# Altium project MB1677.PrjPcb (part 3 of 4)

## Sheet Board_power.SchDoc: Board power
size A4; Date: Not used; ApprovedBy: Not used; CheckedBy: Not used; Author: Not used; CompanyName: STMicroelectronics; DrawnBy: Not used; Engineer: Not used; Organization: Not used; Address1: Not used; Address2: Not used; Address3: Not used; Address4: Not used; DocumentNumber: 5; Revision: Not used; SheetNumber: 5; SheetTotal: 15
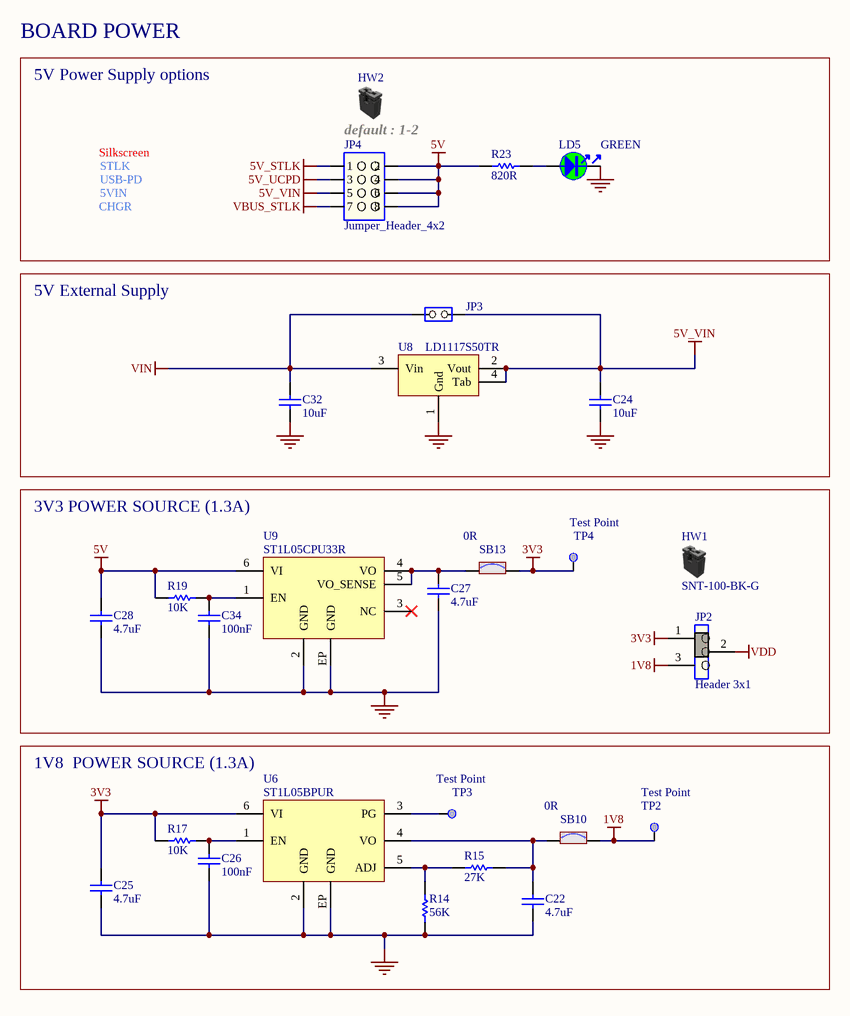
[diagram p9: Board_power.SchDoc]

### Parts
C22  value 4.7uF  [C0603]  (hidden comment: Capacitor)
C24  value 10uF  [C0805]  (hidden comment: Capacitor)
C25  value 4.7uF  [C0603]  (hidden comment: Capacitor)
C26  value 100nF  [C0402]  (hidden comment: Capacitor)
C27  value 4.7uF  [C0603]  (hidden comment: Capacitor)
C28  value 4.7uF  [C0603]  (hidden comment: Capacitor)
C32  value 10uF  [C0805]  (hidden comment: Capacitor)
C34  value 100nF  [C0402]  (hidden comment: Capacitor)
HW1  value SNT-100-BK-G  (hidden comment: Shunt Black 2.54mm)  (mechanical)
HW2  Shunt Black 2.54mm  (value not drawn)  (mechanical)
JP2  value Header 3x1  [CON_SAMTEC_TSW-103-07-F-S]  (hidden comment: Jumper_Header 3x1 Fitted 1-2)
JP3  Jumper_Header 2x1  [CON_SAMTEC_TSW-102-07-G-S]  (value not drawn)
JP4  value Jumper_Header_4x2  [CON_SAMTEC_TSM-104-01-X-DV]  (hidden comment: Jumper_Header 4x2)
LD5  value GREEN  [LED_0603_VISHAY_VLMTG1300-GS08_GREEN_1A2K_H0P8]  (hidden comment: LED_green)
R14  value 56K  [R0402]  (hidden comment: Resistor)
R15  value 27K  [R0402]  (hidden comment: Resistor)
R17  value 10K  [R0402]  (hidden comment: Resistor)
R19  value 10K  [R0402]  (hidden comment: Resistor)
R23  value 820R  [R0603]  (hidden comment: Resistor)
SB10  value 0R  [SOLDER-BRIDGE_R0603-0R]  (hidden comment: SB_ON)
SB13  value 0R  [SOLDER-BRIDGE_R0603-0R]  (hidden comment: SB_ON)
TP2  Test Point  [TP_SMD_2MM]  (no BOM)
TP3  Test Point  [TP_SMD_2MM]  (no BOM)
TP4  Test Point  [TP_SMD_2MM]  (no BOM)
U6  ST1L05BPUR  [ICC_DFN6-EPAD_3X3_P095]
U8  LD1117S50TR  [REG_SOT223-TAB]
U9  ST1L05CPU33R  [ICC_DFN6-EPAD_3X3_P095]

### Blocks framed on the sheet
BOARD POWER: HW2 JP4 LD5 R23
5V External Supply: C24 C32 JP3 U8
3V3 POWER SOURCE (1.3A): C27 C28 C34 HW1 JP2 R19 SB13 TP4 U9
1V8  POWER SOURCE (1.3A): C22 C25 C26 R14 R15 R17 SB10 TP2 TP3 U6

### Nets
1V8: JP2.3 SB10.2 TP2.1
3V3: C25.1 JP2.1 R17.1 SB13.2 TP4.1 U6.6(VI)
5V: C28.2 JP4.2 JP4.4 JP4.6 JP4.8 R19.1 R23.1 U9.6(VI)
5V_STLK: JP4.1
5V_UCPD: JP4.3
5V_VIN: C24.2 JP3.2(NO) JP4.5 U8.2(Vout) U8.4(Tab)
GND: C22.1 C24.1 C25.2 C26.1 C27.1 C28.1 C32.1 C34.1 LD5.2 R14.1 U6.2(GND) U6.EP(GND) U8.1(Gnd) U9.2(GND) U9.EP(GND)
VBUS_STLK: JP4.7
VDD: JP2.2
VIN: C32.2 JP3.1(COMMON) U8.3(Vin)
NetC22_2: C22.2 R15.2 SB10.1 U6.4(VO)
NetC26_2: C26.2 R17.2 U6.1(EN)
NetC27_2: C27.2 SB13.1 U9.4(VO) U9.5(VO_SENSE)
NetC34_2: C34.2 R19.2 U9.1(EN)
NetLD5_1: LD5.1 R23.2
NetR14_2: R14.2 R15.1 U6.5(ADJ)
NetTP3_1: TP3.1 U6.3(PG)

Not connected (* = marked no-connect by the designer): U9 3(NC)*

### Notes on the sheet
- 5V Power Supply options
- Silkscreen
- default : 1-2
- CHGR
- STLK
- USB-PD
- 5VIN

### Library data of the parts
C22 C25 C27 C28 = MCD-00009: Capacitor, MLCC, 4.7uF, 16V, X5R, +/-10%, 0603, T=0.8mm; Manufacturer_Part_Number: CC0603KRX5R7BB475; Manufacturer: YAGEO; Part_Preference: Recommended; Partial_Alternate_Internal_Part_Number: MCD-03565; Alternate_EMS: A; Component_Country_Of_Origin: China; ID: 2471; ShowFields: YES
C24 C32 = MCD-00014: Capacitor, MLCC, 10uF, 25V, X5R, 10%, 0805, T=0,85mm; Manufacturer_Part_Number: CC0805KRX5R8BB106; Manufacturer: YAGEO; Full_Alternate_Internal_Part_Number: MCD-02385; Part_Preference: Recommended; Partial_Alternate_Internal_Part_Number: MCD-03053; Provided_By: SUBCO; Component_Country_Of_Origin: China; ID: 2468; ShowFields: YES
C26 C34 = MCD-00006: Capacitor, MLCC, 100nF, 16V, X7R, +/-10%, 0402, T=0.5mm; Manufacturer_Part_Number: CC0402KRX7R7BB104; Manufacturer: YAGEO; Part_Preference: Recommended; Partial_Alternate_Internal_Part_Number: MCD-03299; Component_Country_Of_Origin: China; ID: 2474; Order_Code_RS: 9402047; ShowFields: YES
HW1 = MCD-00043: SHUNT 2.54mm BLACK; Part_Type: Misc; Part_Preference: Recommended; Manufacturer: SAMTEC; Alternate_Manufacturer: JIUBABA; Alternate_Manufacturer_Part_Number: 316102S111A; Full_Alternate_Internal_Part_Number: MCD-02388; Manufacturer_HQ_COO: Unknown; Partial_Alternate_Internal_Part_Number: MCD-01849; Alternate_EMS: A; Component_Country_Of_Origin: China, Costa Rica, Malaysia, USA, Vietnam; ID: 2551; Order_Code_RS: 158-7784; ShowFields: YES
HW2 = MCD-00043: SHUNT 2.54mm BLACK; Part_Type: Misc; Manufacturer: SAMTEC; Alternate_Manufacturer_Part_Number: 316102S111A; Alternate_Manufacturer: JIUBABA; Full_Alternate_Internal_Part_Number: MCD-02388; Manufacturer_HQ_COO: Unknown; Part_Preference: Recommended; Partial_Alternate_Internal_Part_Number: MCD-01849; Value: SNT-100-BK-G; Provided_By: SUBCO; Alternate_EMS: A; Component_Country_Of_Origin: China, Costa Rica, Malaysia, USA, Vietnam; ID: 2551; Order_Code_RS: 158-7784; ShowFields: YES
JP2 = MCD-00684: Header, 3x1, 2,54mm, VR, TH, Height 5.84mm/2.54mm - Shunt Fitted 1-2 by default; Part_Type: Connector; Part_Preference: Recommended; Manufacturer: SAMTEC; Manufacturer_Part_Number: TSW-103-07-F-S; Partial_Alternate_Internal_Part_Number: MCD-03595, MCD-03723; Alternate_EMS: A; Component_Country_Of_Origin: China, Costa Rica, Malaysia, USA, Vietnam; ID: 3059; Order_Code_RS: 161-2248; ShowFields: YES
JP3 = MCD-00045: Header, 2x1, 2,54mm, VR, TH, Height 5.84mm/2.54mm; Part_Type: Connector; Manufacturer_Part_Number: TSW-102-07-G-S; Manufacturer: SAMTEC; Full_Alternate_Internal_Part_Number: MCD-02390; Part_Preference: Recommended; Partial_Alternate_Internal_Part_Number: MCD-02957, MCD-03720; Provided_By: Subcon; Initial_Board_Reference: MB1274; Remark: 3D KO: BZ: 40098; Component_Country_Of_Origin: China, Costa Rica, Malaysia, USA, Vietnam; ID: 2545; Order_Code_RS: 2505044; ShowFields: YES
JP4 = MCD-00044: Header, 4x2, 2,54mm, VR, SMT, Height 5.84mm/2.54mm; Part_Type: Connector; Part_Preference: Recommended; Manufacturer: SAMTEC; Manufacturer_Part_Number: TSM-104-01-G-DV; Component_Country_Of_Origin: China, Costa Rica, Malaysia, USA, Vietnam; ID: 2548; Order_Code_RS: 2578717; ShowFields: YES
LD5 = MCD-00589: LED Green, 0603 SMD, Fw Voltage = 2.8V - 3.6V; Part_Type: Display; Manufacturer_Part_Number: VLMTG1300-GS08; Manufacturer: VISHAY; Alternate_Manufacturer_Part_Number: LG Q396-PS-35; Alternate_Manufacturer: OSRAM OPTO SEMICONDUCTORS; Part_Preference: Recommended; Order_Code_RS: 7730452; Provided_By: SUBCO; Component_Country_Of_Origin: China; ID: 3157; ShowFields: YES
R14 = MCD-00493: Resistor,56K,0402,1%,1/16W; Part_Preference: Recommended; Manufacturer: YAGEO; Manufacturer_Part_Number: RC0402FR-0756KL; Component_Country_Of_Origin: China; ID: 2784; ShowFields: YES
R15 = MCD-00443: Resistor,27K,0402,1%,1/16W; Part_Preference: Recommended; Manufacturer: YAGEO; Manufacturer_Part_Number: RC0402FR-0727KL; Component_Country_Of_Origin: China; ID: 2834; ShowFields: YES
R17 R19 = MCD-00053: Resistor,10K,0402,1%,1/16W; Manufacturer_Part_Number: RC0402FR-0710KL; Manufacturer: YAGEO; BMS_Part_Number: 9131590; Part_Preference: Recommended; Provided_By: SUBCO; Component_Country_Of_Origin: China; ID: 2539; Order_Code_RS: 9239359; ShowFields: YES
R23 = MCD-00528: Resistor,820R,0603,1%,1/10W; Manufacturer_Part_Number: RC0603FR-07820RL; Manufacturer: YAGEO; BMS_Part_Number: 9129759; Part_Preference: Recommended; Provided_By: SUBCO; Component_Country_Of_Origin: China; ID: 3218; ShowFields: YES
SB10 SB13 = MCD-00071: Resistor, 0R, SB0603, 5%, 0.1W; Manufacturer_Part_Number: RC0603JR-070RL; Manufacturer: YAGEO; Manufacturer_HQ_COO: Unknown; Part_Preference: Recommended; Component_Country_Of_Origin: China; ID: 2521; Order_Code_RS: 199-5647; ShowFields: YES
TP2-TP4 = MCD-00177: Test Point 2mm; Part_Type: Misc; Part_Preference: Recommended; Component_Country_Of_Origin: Unknown; ID: 2690; ShowFields: YES
U6 = MCD-00581: LDO Linear Voltage Regulator IC Positive Adjustable 1 Output Adjustable 1.3A 6-DFN (3x3); BMS_Part_Number: 9176239; Part_Preference: Recommended; Manufacturer: STMICROELECTRONICS; Manufacturer_HQ_COO: EU; Component_Country_Of_Origin: Malaysia; ID: 3163; Order_Code_RS: 188-9209; ShowFields: YES
U8 = MCD-00088: IC REG LDO 5V 0.8A SOT223; Manufacturer: STMICROELECTRONICS; BMS_Part_Number: 9176133; Manufacturer_HQ_COO: EU; Part_Preference: Recommended; Provided_By: SUBCO with ST control; Component_Country_Of_Origin: China; ID: 2503; Order_Code_RS: 165-7748; ShowFields: YES
U9 = MCD-01025: LDO, 3.3V, 1.3A, Very low quiescent current BiCMOS voltage regulator; Part_Type: IC; Manufacturer: STMICROELECTRONICS; BMS_Part_Number: 9176246; Manufacturer_HQ_COO: EU; Part_Preference: Recommended; Provided_By: SUBCO with ST control; Component_Country_Of_Origin: Malaysia; ID: 2998; ShowFields: YES

## Sheet STM32_microcontroller_power.SchDoc: STM32 microcontroller power
size A4; Date: Not used; ApprovedBy: Not used; CheckedBy: Not used; Author: Not used; CompanyName: STMicroelectronics; DrawnBy: Not used; Engineer: Not used; Organization: Not used; Address1: Not used; Address2: Not used; Address3: Not used; Address4: Not used; DocumentNumber: 4; Revision: Not used; SheetNumber: 4; SheetTotal: 15
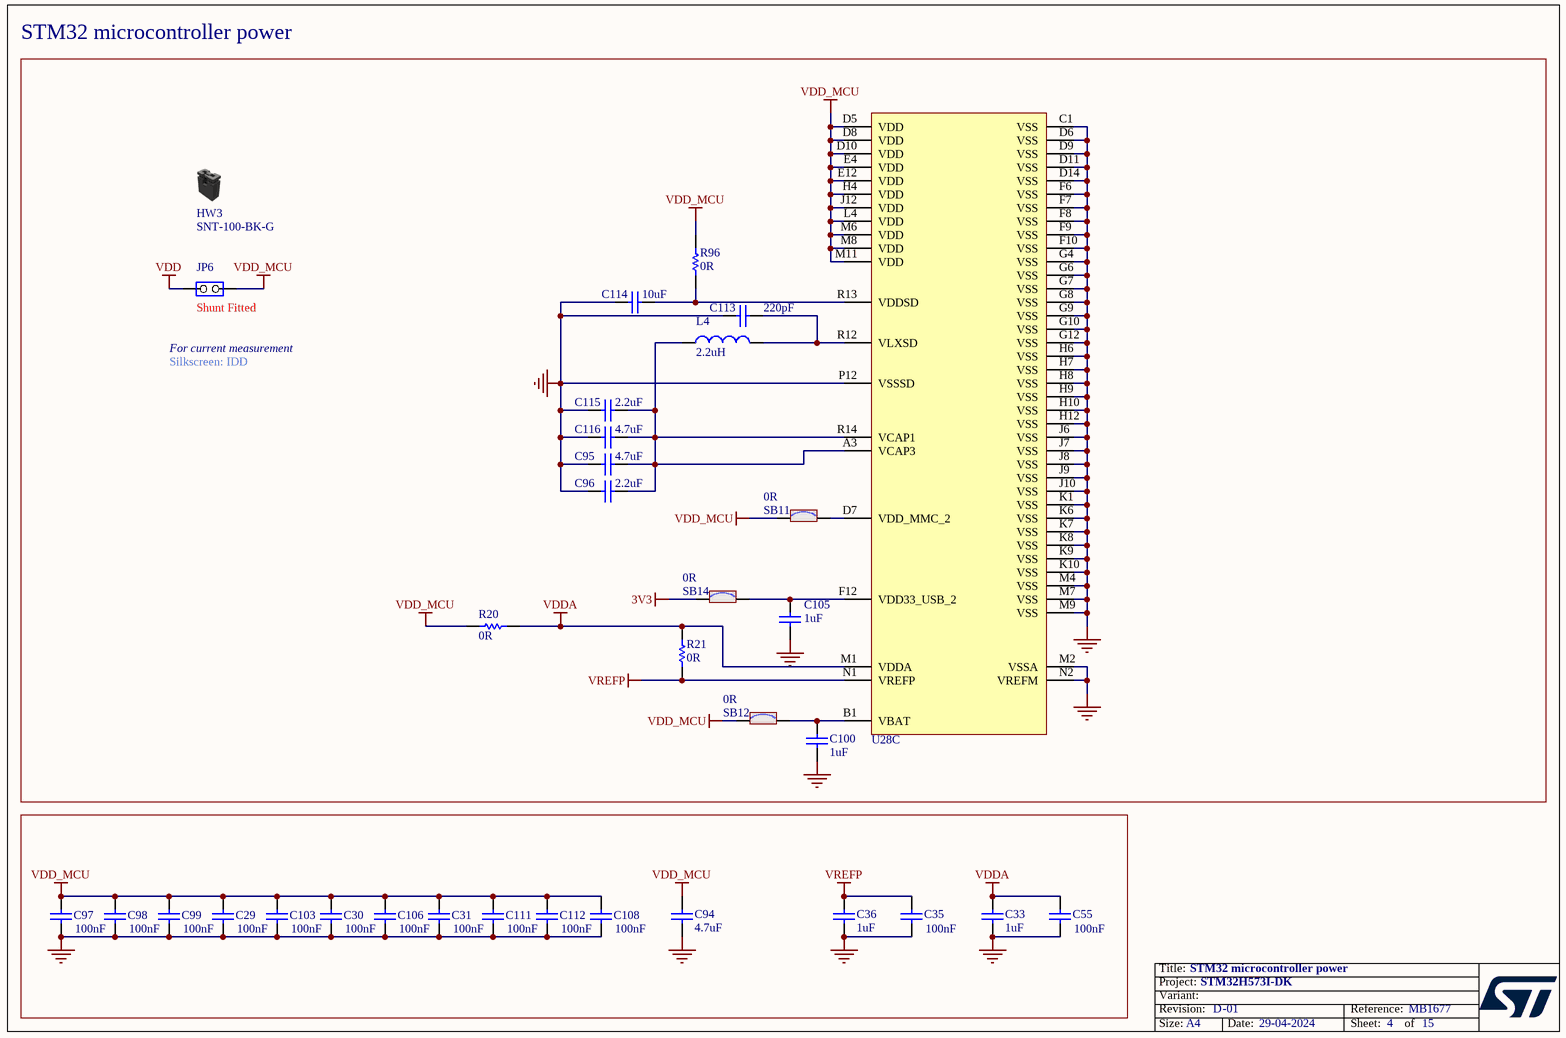
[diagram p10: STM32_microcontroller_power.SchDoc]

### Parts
C29  value 100nF  [C0402]  (hidden comment: Capacitor)
C30  value 100nF  [C0402]  (hidden comment: Capacitor)
C31  value 100nF  [C0402]  (hidden comment: Capacitor)
C33  value 1uF  [C0402]  (hidden comment: Capacitor)
C35  value 100nF  [C0402]  (hidden comment: Capacitor)
C36  value 1uF  [C0402]  (hidden comment: Capacitor)
C55  value 100nF  [C0402]  (hidden comment: Capacitor)
C94  value 4.7uF  [C0603]  (hidden comment: Capacitor)
C95  value 4.7uF  [C0402]  (hidden comment: Capacitor)
C96  value 2.2uF  [C0402]  (hidden comment: Capacitor)
C97  value 100nF  [C0402]  (hidden comment: Capacitor)
C98  value 100nF  [C0402]  (hidden comment: Capacitor)
C99  value 100nF  [C0402]  (hidden comment: Capacitor)
C100  value 1uF  [C0402]  (hidden comment: Capacitor)
C103  value 100nF  [C0402]  (hidden comment: Capacitor)
C105  value 1uF  [C0603]  (hidden comment: Capacitor)
C106  value 100nF  [C0402]  (hidden comment: Capacitor)
C108  value 100nF  [C0402]  (hidden comment: Capacitor)
C111  value 100nF  [C0402]  (hidden comment: Capacitor)
C112  value 100nF  [C0402]  (hidden comment: Capacitor)
C113  value 220pF  [C0402]  (hidden comment: Capacitor)
C114  value 10uF  [C0402]  (hidden comment: Capacitor)
C115  value 2.2uF  [C0402]  (hidden comment: Capacitor)
C116  value 4.7uF  [C0402]  (hidden comment: Capacitor)
HW3  value SNT-100-BK-G  (hidden comment: Shunt Black 2.54mm)  (mechanical)
JP6  Jumper_Header 2x1  [CON_SAMTEC_TSW-102-07-G-S]  (value not drawn)
L4  value 2.2uH  [L0805_H0P9]  (hidden comment: Inductor)
R20  value 0R  [R0603]  (hidden comment: Resistor)
R21  value 0R  [R0603]  (hidden comment: Resistor)
R96  value 0R  [R0603]  (hidden comment: Resistor)
SB11  value 0R  [SOLDER-BRIDGE_R0603-0R]  (hidden comment: SB_ON)
SB12  value 0R  [SOLDER-BRIDGE_R0603-0R]  (hidden comment: SB_ON)
SB14  value 0R  [SOLDER-BRIDGE_R0603-0R]  (hidden comment: SB_ON)
U28  STM32H573IIK3Q  [ICC_UFBGA201_176+25_10X10_P065]  (value not drawn)  (part C of 3)

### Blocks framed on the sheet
STM32 microcontroller power: C95 C96 C100 C105 C113-C116 HW3 JP6 L4 R20 R21 R96 SB11 SB12 SB14 U28

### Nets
3V3: SB14.1
GND: C29.2 C30.2 C31.2 C33.1 C35.1 C36.1 C55.1 C94.1 C95.2 C96.1 C97.2 C98.2 C99.2 C100.1 C103.2 C105.1 C106.2 C108.2 C111.2 C112.2 C113.1 C114.1 C115.1 C116.2 U28.C1(VSS) U28.D6(VSS) U28.D9(VSS) U28.D11(VSS) U28.D14(VSS) U28.F6(VSS) U28.F7(VSS) U28.F8(VSS) U28.F9(VSS) U28.F10(VSS) U28.G4(VSS) U28.G6(VSS) U28.G7(VSS) U28.G8(VSS) U28.G9(VSS) U28.G10(VSS) U28.G12(VSS) U28.H6(VSS) U28.H7(VSS) U28.H8(VSS) U28.H9(VSS) U28.H10(VSS) U28.H12(VSS) U28.J6(VSS) U28.J7(VSS) U28.J8(VSS) U28.J9(VSS) U28.J10(VSS) U28.K1(VSS) U28.K6(VSS) U28.K7(VSS) U28.K8(VSS) U28.K9(VSS) U28.K10(VSS) U28.M2(VSSA) U28.M4(VSS) U28.M7(VSS) U28.M9(VSS) U28.N2(VREFM) U28.P12(VSSSD)
VDD: JP6.1(COMMON)
VDD_MCU: C29.1 C30.1 C31.1 C94.2 C97.1 C98.1 C99.1 C103.1 C106.1 C108.1 C111.1 C112.1 JP6.2(NO) R20.1 R96.2 SB11.1 SB12.1 U28.D5(VDD) U28.D8(VDD) U28.D10(VDD) U28.E4(VDD) U28.E12(VDD) U28.H4(VDD) U28.J12(VDD) U28.L4(VDD) U28.M6(VDD) U28.M8(VDD) U28.M11(VDD)
VDDA: C33.2 C55.2 R20.2 R21.1 U28.M1(VDDA)
VREFP: C35.2 C36.2 R21.2 U28.N1(VREFP)
NetC95_1: C95.1 C96.2 C115.2 C116.1 L4.1 U28.A3(VCAP3) U28.R14(VCAP1)
NetC100_2: C100.2 SB12.2 U28.B1(VBAT)
NetC105_2: C105.2 SB14.2 U28.F12(VDD33_USB_2)
NetC113_2: C113.2 L4.2 U28.R12(VLXSD)
NetC114_2: C114.2 R96.1 U28.R13(VDDSD)
NetSB11_2: SB11.2 U28.D7(VDD_MMC_2)

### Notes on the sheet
- (near JP6) Shunt Fitted
- For current measurement
- Silkscreen: IDD

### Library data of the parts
C29-C31 C35 C55 C97-C99 C103 C106 C108 C111 C112 = MCD-00006: as C26 on sheet Board_power
C33 C36 C100 = MCD-01722: Capacitor, 1uF, 10V, X5R, 10%, 0402, T=0.5mm; Manufacturer_Part_Number: CC0402KRX5R6BB105; Manufacturer: YAGEO; Part_Preference: Recommended; Provided_By: SUBCO; Component_Country_Of_Origin: China; ID: 3822; ShowFields: YES
C94 = MCD-00009: as C22 on sheet Board_power
C95 C116 = MCD-01356: Capacitor, MLCC, 4.7uF, 6V3, X5R, +/-20%, 0402, T=0,5mm; Part_Preference: Recommended; Manufacturer: MURATA; Manufacturer_Part_Number: GRM155R60J475ME47; Alternate_Manufacturer_Part_Number: GRM155R60J475ME87; Order_Code_RS: 814-5230; Component_Country_Of_Origin: Japan°°; ID: 3456; ShowFields: YES
C96 C115 = MCD-01823: Capacitor,MLCC, 2.2uF, 6V3, X5R,+/-10%, 0402, T=0.5mm; Part_Preference: Recommended; Manufacturer: MURATA; Manufacturer_Part_Number: GRM155R60J225KE95D; Partial_Alternate_Internal_Part_Number: MCD-03566; Order_Code_RS: 172-6478; Component_Country_Of_Origin: Japan°°; ID: 3923; ShowFields: YES
C105 = MCD-00010: Capacitor, MLCC, 1uF, 16V, X5R, +/-10%, 0603, T=0.8mm; Manufacturer_Part_Number: CC0603KRX5R7BB105; Manufacturer: YAGEO; Part_Preference: Recommended; Component_Country_Of_Origin: China; ID: 2470; Order_Code_RS: 2370680; ShowFields: YES
C113 = MCD-01225: Capacitor, MLCC, 220pF, 50V, NPO, +/-5%, 0402, T=0,5mm; Part_Preference: Recommended; Manufacturer: YAGEO; Manufacturer_Part_Number: CC0402JRNPO9BN221; Order_Code_RS: 616-9284; Component_Country_Of_Origin: China; ID: 3272; ShowFields: YES
C114 = MCD-01355: Capacitor, MLCC, 10uF, 4V, X5R, +/-20%, 0402, T=0,5mm; Part_Preference: Recommended; Manufacturer: MURATA; Manufacturer_Part_Number: GRM155R60G106ME44; Partial_Alternate_Internal_Part_Number: MCD-01716; Order_Code_RS: 172-6477; Alternate_EMS: A; Component_Country_Of_Origin: Japan°°; ID: 3455; ShowFields: YES
HW3 = MCD-00043: SHUNT 2.54mm BLACK; Manufacturer: SAMTEC; Part_Type: Misc; Alternate_Manufacturer_Part_Number: 316102S111A; Alternate_Manufacturer: JIUBABA; Full_Alternate_Internal_Part_Number: MCD-02388; Manufacturer_HQ_COO: Unknown; Part_Preference: Recommended; Partial_Alternate_Internal_Part_Number: MCD-01849; Provided_By: SUBCO; Alternate_EMS: A; Component_Country_Of_Origin: China, Costa Rica, Malaysia, USA, Vietnam; ID: 2551; Order_Code_RS: 158-7784; ShowFields: YES
JP6 = MCD-00045: Header, 2x1, 2,54mm, VR, TH, Height 5.84mm/2.54mm; Manufacturer_Part_Number: TSW-102-07-G-S; Manufacturer: SAMTEC; Part_Type: Connector; Alternate_Manufacturer_Part_Number: 313102S111116; Alternate_Manufacturer: JIUBABA; Full_Alternate_Internal_Part_Number: MCD-02390; Part_Preference: Recommended; Partial_Alternate_Internal_Part_Number: MCD-02957, MCD-03720; Provided_By: SUBCO; Component_Country_Of_Origin: China, Costa Rica, Malaysia, USA, Vietnam; ID: 2545; Order_Code_RS: 2505044; ShowFields: YES
L4 = MCD-03791: Inductor 2.2uH, +/-20%, 1.8A, 0.138Ω, 0805; Part_Preference: Recommended; Manufacturer: MURATA; Manufacturer_Part_Number: DFE21CCN2R2MELL; Component_Country_Of_Origin: Vietnam; ShowFields: YES; ID: 5907
R20 R21 = MCD-00056: Resistor,0R,0603,5%,1/10W; Manufacturer_Part_Number: RC0603JR-070RL; Manufacturer: YAGEO; Part_Preference: Recommended; Provided_By: SUBCO; Component_Country_Of_Origin: China; ID: 2536; Order_Code_RS: 9233130RL; ShowFields: YES
R96 = MCD-00056: Resistor,0R,0603,5%,1/10W; Part_Preference: Recommended; Manufacturer: YAGEO; Manufacturer_Part_Number: RC0603JR-070RL; Order_Code_RS: 9233130RL; Component_Country_Of_Origin: China; ID: 2536; ShowFields: YES
SB11 SB12 SB14 = MCD-00071: as SB10 on sheet Board_power
U28 = MCD-02379: MCU, Arm Cortex-M33, 250MHz, 32-bit MCU, 2MB Flash, 640KB SRAM, Crypto; Part_Type: IC; Manufacturer: STMICROELECTRONICS; Part_Preference: Recommended; Component_Country_Of_Origin: Unknown; ID: 4485; ShowFields: YES

## Sheet STM32_microcontroller_IOs.SchDoc: STM32 microcontroller IOs
size A3; Date: Not used; ApprovedBy: Not used; CheckedBy: Not used; Author: Not used; CompanyName: STMicroelectronics; DrawnBy: Not used; Engineer: Not used; Organization: Not used; Address1: Not used; Address2: Not used; Address3: Not used; Address4: Not used; DocumentNumber: 3; Revision: Not used; SheetNumber: 3; SheetTotal: 15
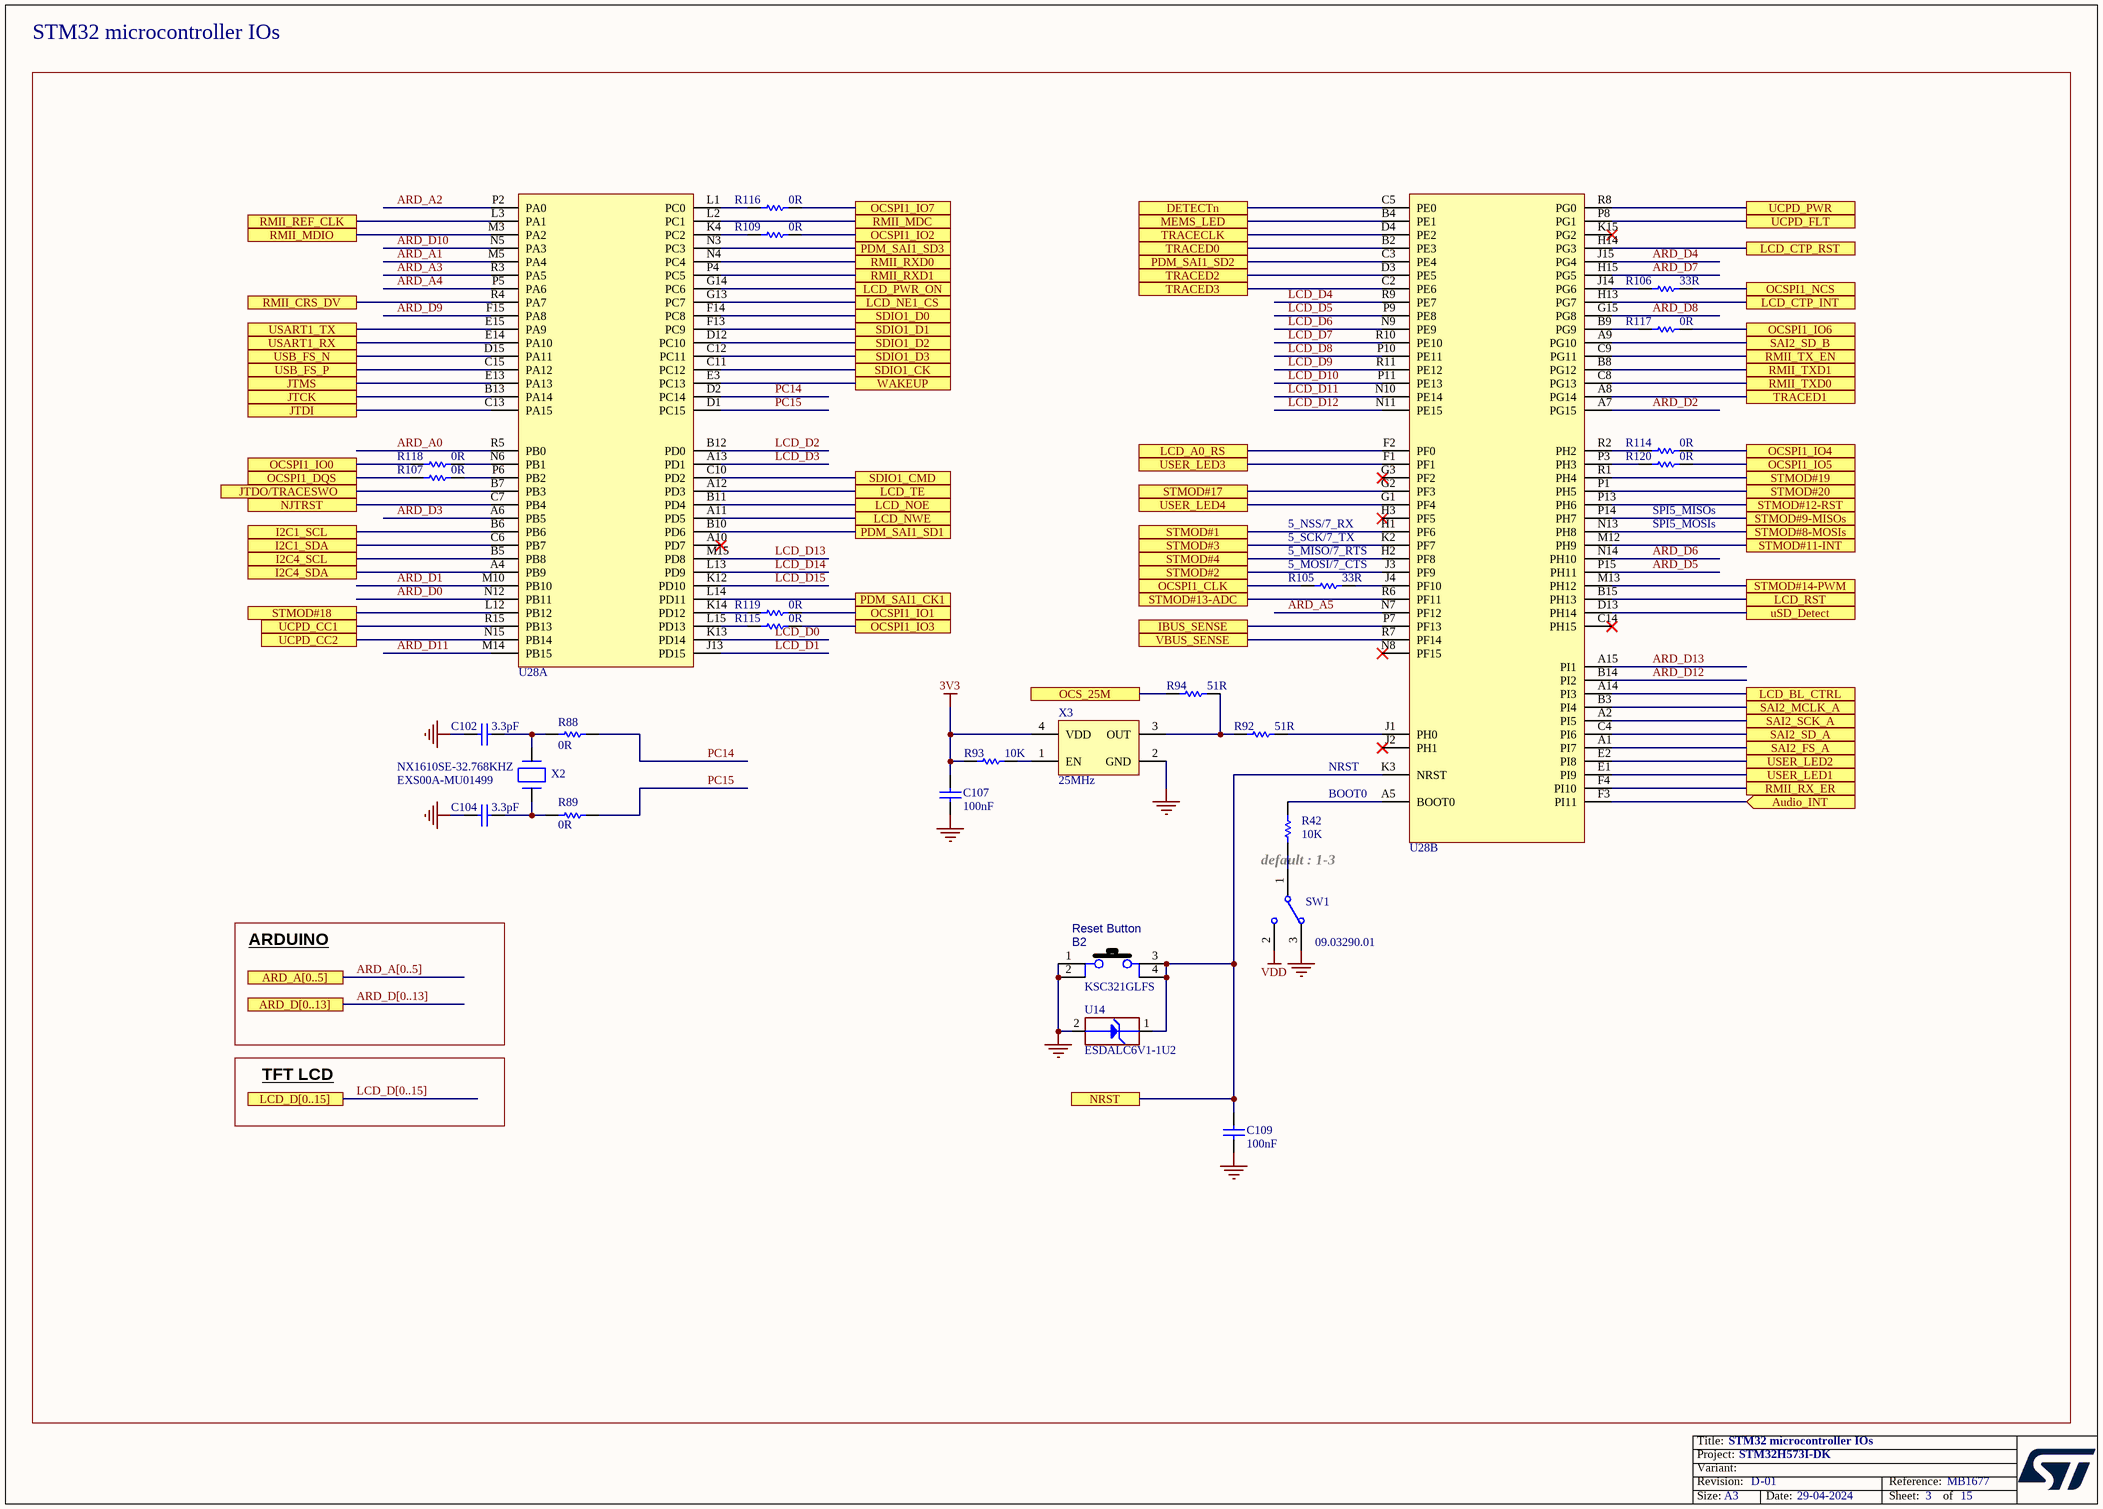
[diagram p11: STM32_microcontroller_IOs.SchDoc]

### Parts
B2  value KSC321GLFS  [SWI_C&K_KSC321GLFS_BLACK]  (hidden comment: SW_BLACK_KSC321GLFS)
C102  value 3.3pF  [C0402]  (hidden comment: Capacitor)
C104  value 3.3pF  [C0402]  (hidden comment: Capacitor)
C107  value 100nF  [C0402]  (hidden comment: Capacitor)
C109  value 100nF  [C0402]  (hidden comment: Capacitor)
R42  value 10K  [R0402]  (hidden comment: Resistor)
R88  value 0R  [R0402]  (hidden comment: Resistor)
R89  value 0R  [R0402]  (hidden comment: Resistor)
R92  value 51R  [R0402]  (hidden comment: Resistor)
R93  value 10K  [R0402]  (hidden comment: Resistor)
R94  value 51R  [R0402]  (hidden comment: Resistor)
R105  value 33R  [R0402]  (hidden comment: Resistor)
R106  value 33R  [R0402]  (hidden comment: Resistor)
R107  value 0R  [R0402]  (hidden comment: Resistor)
R109  value 0R  [R0402]  (hidden comment: Resistor)
R114  value 0R  [R0402]  (hidden comment: Resistor)
R115  value 0R  [R0402]  (hidden comment: Resistor)
R116  value 0R  [R0402]  (hidden comment: Resistor)
R117  value 0R  [R0402]  (hidden comment: Resistor)
R118  value 0R  [R0402]  (hidden comment: Resistor)
R119  value 0R  [R0402]  (hidden comment: Resistor)
R120  value 0R  [R0402]  (hidden comment: Resistor)
SW1  value 09.03290.01  [SWI_EAO_09-03290-01_EXTENDED_STRAIGHT_BLACK]  (hidden comment: SW_MECA_1K2)
U14  value ESDALC6V1-1U2  [ESD_ST0201]  (hidden comment: ESD-TRANSIL)
U28  STM32H573IIK3Q  [ICC_UFBGA201_176+25_10X10_P065]  (value not drawn)  (parts A,B of 3)
X2  XTAL_2_PINS  [CRY_NX1610SE_2P]  (value not drawn)
X3  value 25MHz  [OSC_NDK_NZ2520SB_4P]  (hidden comment: OSCILLATOR_4_PINS)

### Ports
ARD_A[0..5], ARD_D[0..13], Audio_INT (in), DETECTn, I2C1_SCL, I2C1_SDA, I2C4_SCL, I2C4_SDA, IBUS_SENSE, JTCK, JTDI, JTDO/TRACESWO, JTMS, LCD_A0_RS, LCD_BL_CTRL, LCD_CTP_INT, LCD_CTP_RST, LCD_D[0..15], LCD_NE1_CS, LCD_NOE, LCD_NWE, LCD_PWR_ON, LCD_RST, LCD_TE, MEMS_LED, NJTRST, NRST, OCS_25M, OCSPI1_CLK, OCSPI1_DQS, OCSPI1_IO0, OCSPI1_IO1, OCSPI1_IO2, OCSPI1_IO3, OCSPI1_IO4, OCSPI1_IO5, OCSPI1_IO6, OCSPI1_IO7, OCSPI1_NCS, PDM_SAI1_CK1, PDM_SAI1_SD1, PDM_SAI1_SD2, PDM_SAI1_SD3, RMII_CRS_DV, RMII_MDC, RMII_MDIO, RMII_REF_CLK, RMII_RX_ER, RMII_RXD0, RMII_RXD1, RMII_TX_EN, RMII_TXD0, RMII_TXD1, SAI2_FS_A, SAI2_MCLK_A, SAI2_SCK_A, SAI2_SD_A, SAI2_SD_B, SDIO1_CK, SDIO1_CMD, SDIO1_D0, SDIO1_D1, SDIO1_D2, SDIO1_D3, STMOD#1, STMOD#2, STMOD#3, STMOD#4, STMOD#8-MOSIs, STMOD#9-MISOs, STMOD#11-INT, STMOD#12-RST, STMOD#13-ADC, STMOD#14-PWM, STMOD#17, STMOD#18, STMOD#19, STMOD#20, TRACECLK, TRACED0, TRACED1, TRACED2, TRACED3, UCPD_CC1, UCPD_CC2, UCPD_FLT, UCPD_PWR, USART1_RX, USART1_TX, USB_FS_N, USB_FS_P, uSD_Detect, USER_LED1, USER_LED2, USER_LED3, USER_LED4, VBUS_SENSE, WAKEUP

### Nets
3V3: C107.2 R93.1 X3.4(VDD)
GND: B2.1 B2.2 C102.1 C104.1 C107.1 C109.1 SW1.3 U14.2(GND) X3.2(GND)
VDD: SW1.2
ARD_A0: U28.R5(PB0)
ARD_A1: U28.M5(PA4)
ARD_A2: U28.P2(PA0)
ARD_A3: U28.R3(PA5)
ARD_A4: U28.P5(PA6)
ARD_A5: U28.N7(PF12)
ARD_D0: U28.N12(PB11)
ARD_D1: U28.M10(PB10)
ARD_D2: U28.A7(PG15)
ARD_D3: U28.A6(PB5)
ARD_D4: U28.J15(PG4)
ARD_D5: U28.P15(PH11)
ARD_D6: U28.N14(PH10)
ARD_D7: U28.H15(PG5)
ARD_D8: U28.G15(PG8)
ARD_D9: U28.F15(PA8)
ARD_D10: U28.N5(PA3)
ARD_D11: U28.M14(PB15)
ARD_D12: U28.B14(PI2)
ARD_D13: U28.A15(PI1)
Audio_INT: U28.F3(PI11) ; port Audio_INT
DETECTn: U28.C5(PE0) ; port DETECTn
I2C1_SCL: U28.B6(PB6) ; port I2C1_SCL
I2C1_SDA: U28.C6(PB7) ; port I2C1_SDA
I2C4_SCL: U28.B5(PB8) ; port I2C4_SCL
I2C4_SDA: U28.A4(PB9) ; port I2C4_SDA
IBUS_SENSE: U28.P7(PF13) ; port IBUS_SENSE
JTCK: U28.B13(PA14) ; port JTCK
JTDI: U28.C13(PA15) ; port JTDI
JTDO: U28.B7(PB3) ; port JTDO/TRACESWO
JTMS: U28.E13(PA13) ; port JTMS
LCD_A0_RS: U28.F2(PF0) ; port LCD_A0_RS
LCD_BL_CTRL: U28.A14(PI3) ; port LCD_BL_CTRL
LCD_CTP_INT: U28.H13(PG7) ; port LCD_CTP_INT
LCD_CTP_RST: U28.H14(PG3) ; port LCD_CTP_RST
LCD_D0: U28.K13(PD14)
LCD_D1: U28.J13(PD15)
LCD_D2: U28.B12(PD0)
LCD_D3: U28.A13(PD1)
LCD_D4: U28.R9(PE7)
LCD_D5: U28.P9(PE8)
LCD_D6: U28.N9(PE9)
LCD_D7: U28.R10(PE10)
LCD_D8: U28.P10(PE11)
LCD_D9: U28.R11(PE12)
LCD_D10: U28.P11(PE13)
LCD_D11: U28.N10(PE14)
LCD_D12: U28.N11(PE15)
LCD_D13: U28.M15(PD8)
LCD_D14: U28.L13(PD9)
LCD_D15: U28.K12(PD10)
LCD_NE1_CS: U28.G13(PC7) ; port LCD_NE1_CS
LCD_NOE: U28.B11(PD4) ; port LCD_NOE
LCD_NWE: U28.A11(PD5) ; port LCD_NWE
LCD_PWR_ON: U28.G14(PC6) ; port LCD_PWR_ON
LCD_RST: U28.B15(PH13) ; port LCD_RST
LCD_TE: U28.A12(PD3) ; port LCD_TE
MEMS_LED: U28.B4(PE1) ; port MEMS_LED
NJTRST: U28.C7(PB4) ; port NJTRST
NRST: B2.3 B2.4 C109.2 U14.1(IO1) U28.K3(NRST) ; port NRST
OCS_25M: R94.1 ; port OCS_25M
OCSPI1_CLK: R105.1 ; port OCSPI1_CLK
OCSPI1_DQS: R107.1 ; port OCSPI1_DQS
OCSPI1_IO0: R118.1 ; port OCSPI1_IO0
OCSPI1_IO1: R119.2 ; port OCSPI1_IO1
OCSPI1_IO2: R109.2 ; port OCSPI1_IO2
OCSPI1_IO3: R115.2 ; port OCSPI1_IO3
OCSPI1_IO4: R114.2 ; port OCSPI1_IO4
OCSPI1_IO5: R120.2 ; port OCSPI1_IO5
OCSPI1_IO6: R117.2 ; port OCSPI1_IO6
OCSPI1_IO7: R116.2 ; port OCSPI1_IO7
OCSPI1_NCS: R106.2 ; port OCSPI1_NCS
PC14: R88.2 U28.D2(PC14)
PC15: R89.2 U28.D1(PC15)
PDM_SAI1_CK1: U28.L14(PD11) ; port PDM_SAI1_CK1
PDM_SAI1_SD1: U28.B10(PD6) ; port PDM_SAI1_SD1
PDM_SAI1_SD2: U28.C3(PE4) ; port PDM_SAI1_SD2
PDM_SAI1_SD3: U28.N3(PC3) ; port PDM_SAI1_SD3
PMOD11: U28.M12(PH9) ; port STMOD#11-INT
PMOD12: U28.P13(PH6) ; port STMOD#12-RST
RMII_CRS_DV: U28.R4(PA7) ; port RMII_CRS_DV
RMII_MDC: U28.L2(PC1) ; port RMII_MDC
RMII_MDIO: U28.M3(PA2) ; port RMII_MDIO
RMII_REF_CLK: U28.L3(PA1) ; port RMII_REF_CLK
RMII_RX_ER: U28.F4(PI10) ; port RMII_RX_ER
RMII_RXD0: U28.N4(PC4) ; port RMII_RXD0
RMII_RXD1: U28.P4(PC5) ; port RMII_RXD1
RMII_TX_EN: U28.C9(PG11) ; port RMII_TX_EN
RMII_TXD0: U28.C8(PG13) ; port RMII_TXD0
RMII_TXD1: U28.B8(PG12) ; port RMII_TXD1
SAI2_FS_A: U28.A1(PI7) ; port SAI2_FS_A
SAI2_MCLK_A: U28.B3(PI4) ; port SAI2_MCLK_A
SAI2_SCK_A: U28.A2(PI5) ; port SAI2_SCK_A
SAI2_SD_A: U28.C4(PI6) ; port SAI2_SD_A
SAI2_SD_B: U28.A9(PG10) ; port SAI2_SD_B
SDIO1_CK: U28.C11(PC12) ; port SDIO1_CK
SDIO1_CMD: U28.C10(PD2) ; port SDIO1_CMD
SDIO1_D0: U28.F14(PC8) ; port SDIO1_D0
SDIO1_D1: U28.F13(PC9) ; port SDIO1_D1
SDIO1_D2: U28.D12(PC10) ; port SDIO1_D2
SDIO1_D3: U28.C12(PC11) ; port SDIO1_D3
STMOD#1: U28.H1(PF6) ; port STMOD#1
STMOD#2: U28.J3(PF9) ; port STMOD#2
STMOD#3: U28.K2(PF7) ; port STMOD#3
STMOD#4: U28.H2(PF8) ; port STMOD#4
STMOD#8-MOSIs: U28.N13(PH8) ; port STMOD#8-MOSIs
STMOD#9-MISOs: U28.P14(PH7) ; port STMOD#9-MISOs
STMOD#13-ADC: U28.R6(PF11) ; port STMOD#13-ADC
STMOD#14-PWM: U28.M13(PH12) ; port STMOD#14-PWM
STMOD#17: U28.G2(PF3) ; port STMOD#17
STMOD#18: U28.L12(PB12) ; port STMOD#18
STMOD#19: U28.R1(PH4) ; port STMOD#19
STMOD#20: U28.P1(PH5) ; port STMOD#20
TRACECLK: U28.D4(PE2) ; port TRACECLK
TRACED0: U28.B2(PE3) ; port TRACED0
TRACED1: U28.A8(PG14) ; port TRACED1
TRACED2: U28.D3(PE5) ; port TRACED2
TRACED3: U28.C2(PE6) ; port TRACED3
UCPD_CC1: U28.R15(PB13) ; port UCPD_CC1
UCPD_CC2: U28.N15(PB14) ; port UCPD_CC2
UCPD_FLT: U28.P8(PG1) ; port UCPD_FLT
UCPD_PWR: U28.R8(PG0) ; port UCPD_PWR
USART1_RX: U28.E14(PA10) ; port USART1_RX
USART1_TX: U28.E15(PA9) ; port USART1_TX
USB_FS_N: U28.D15(PA11) ; port USB_FS_N
USB_FS_P: U28.C15(PA12) ; port USB_FS_P
uSD_Detect: U28.D13(PH14) ; port uSD_Detect
USER_LED1: U28.E1(PI9) ; port USER_LED1
USER_LED2: U28.E2(PI8) ; port USER_LED2
USER_LED3: U28.F1(PF1) ; port USER_LED3
USER_LED4: U28.G1(PF4) ; port USER_LED4
VBUS_SENSE: U28.R7(PF14) ; port VBUS_SENSE
WAKEUP: U28.E3(PC13) ; port WAKEUP
NetC102_2: C102.2 R88.1 X2.2(X2)
NetC104_2: C104.2 R89.1 X2.1(X1)
NetR42_1: R42.1 U28.A5(BOOT0)
NetR42_2: R42.2 SW1.1
NetR92_1: R92.1 R94.2 X3.3(OUT)
NetR92_2: R92.2 U28.J1(PH0)
NetR93_2: R93.2 X3.1(EN)
NetR105_2: R105.2 U28.J4(PF10)
NetR106_1: R106.1 U28.J14(PG6)
NetR107_2: R107.2 U28.P6(PB2)
NetR109_1: R109.1 U28.K4(PC2)
NetR114_1: R114.1 U28.R2(PH2)
NetR115_1: R115.1 U28.L15(PD13)
NetR116_1: R116.1 U28.L1(PC0)
NetR117_1: R117.1 U28.B9(PG9)
NetR118_2: R118.2 U28.N6(PB1)
NetR119_1: R119.1 U28.K14(PD12)
NetR120_1: R120.1 U28.P3(PH3)

Not connected (* = marked no-connect by the designer): U28 A10(PD7)* C14(PH15)* G3(PF2)* H3(PF5)* J2(PH1)* K15(PG2)* N8(PF15)*

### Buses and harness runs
bus ARD_A[0..5] = port ARD_A[0..5]
bus ARD_D[0..13] = port ARD_D[0..13]
bus LCD_D[0..15] = port LCD_D[0..15]

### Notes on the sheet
- STM32 microcontroller IOs
- SPI5_MISOs
- 5_NSS/7_RX
- 5_SCK/7_TX
- (near R105) 5_MISO/7_RTS
- (near R105) 5_MOSI/7_CTS
- SPI5_MOSIs
- EXS00A-MU01499
- NX1610SE-32.768KHZ
- NRST
- BOOT0
- (near R42) default : 1-3
- ARDUINO
- (near B2) Reset Button
- TFT LCD

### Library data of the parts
B2 = MCD-00175: Switch HW BLACK High3.5mm 2Newtons; Part_Type: Misc; Part_Preference: Recommended; Manufacturer: C&K; Component_Country_Of_Origin: France; ShowFields: YES; ID: 2692; Order_Code_RS: 894-9095
C102 C104 = MCD-01775: Capacitor, MLCC, 3.3pF, 50V, NPO, +/-0.1pF, 0402, T=0.5mm; Part_Preference: Recommended; Manufacturer: YAGEO; Manufacturer_Part_Number: CC0402BRNPO9BN3R3; Component_Country_Of_Origin: China; ShowFields: YES; ID: 3875
C107 C109 = MCD-00006: as C26 on sheet Board_power
R42 = MCD-00053: as R17 on sheet Board_power
R88 R89 R107 R109 R114-R120 = MCD-00052: Resistor,0R,0402,5%,1/16W; Manufacturer_Part_Number: RC0402JR-070RL; Manufacturer: YAGEO; Part_Preference: Recommended; Provided_By: SUBCO; Component_Country_Of_Origin: China; ID: 2540; Order_Code_RS: 9232516RL; ShowFields: YES
R92 R94 = MCD-00485: Resistor,51R,0402,1%,1/16W; Manufacturer_Part_Number: RC0402FR-0751RL; Manufacturer: YAGEO; Part_Preference: Recommended; ECCN_US: EAR99; ECCN_EU: NEC; Provided_By: SUBCO; Component_Country_Of_Origin: China; ID: 2790; ShowFields: YES
R93 = MCD-00053: Resistor,10K,0402,1%,1/16W; Manufacturer_Part_Number: RC0402FR-0710KL; Manufacturer: YAGEO; BMS_Part_Number: 9131590; Part_Preference: Recommended; ECCN_US: EAR99; ECCN_EU: NEC; Provided_By: SUBCO; Component_Country_Of_Origin: China; ID: 2539; Order_Code_RS: 9239359; ShowFields: YES
R105 R106 = MCD-00455: Resistor,33R,0402,1%,1/16W; Manufacturer_Part_Number: RC0402FR-0733RL; Manufacturer: YAGEO; Part_Preference: Recommended; Provided_By: SUBCO; ECCN_US: EAR99; ECCN_EU: NEC; Component_Country_Of_Origin: China; ID: 2821; ShowFields: YES
SW1 = MCD-00566: Mechanical Slide Switches 1K2 BLK ACT GOLD STRT MNT; Part_Type: Misc; Manufacturer: EAO; Part_Preference: Recommended; Provided_By: SUBCO; Component_Country_Of_Origin: Switzerland°°; ID: 3181; Order_Code_RS: 204-7865; ShowFields: YES
U14 = MCD-00170: ESD protection 6V1; Part_Type: Diode; Manufacturer: STMICROELECTRONICS; BMS_Part_Number: 9151132; Manufacturer_HQ_COO: EU; Part_Preference: Recommended; Provided_By: SUBCO with ST control; Component_Country_Of_Origin: China; ID: 2696; Order_Code_RS: 795-8404; ShowFields: YES
U28 = MCD-02379: as U28 on sheet STM32_microcontroller_power
X2 = MCD-02291: Crystal, 32.768kHz, 9pF, +/-20ppm, 70KR, 1.6x1mm; Part_Type: Crystal_Osc; Part_Preference: Recommended; Manufacturer: NDK; Manufacturer_Part_Number: NX1610SE-32.768KHZ-EXS00A-MU01499; Component_Country_Of_Origin: Unknown; ShowFields: YES; ID: 4391
X3 = MCD-00597: Oscillator 25Mhz, +-50ppm, Vcc:3.3V typ, square wave: [0.1Vcc;0.9Vcc], Enable pin, SMD; Part_Type: Crystal_Osc; Manufacturer_Part_Number: NZ2520SH-25MHZ-END4869C; Manufacturer: NDK; Alternate_Manufacturer_Part_Number: NZ2520SB 25MHz END4869B; BMS_Part_Number: 9157050; Part_Preference: Recommended; ECCN_US: EAR99; ECCN_EU: NEC; Provided_By: SUBCO; Component_Country_Of_Origin: Unknown; ID: 3148; ShowFields: YES

## Sheet USB-PD.SchDoc: USB-PD
size A3; Date: Not used; ApprovedBy: Not used; CheckedBy: Not used; Author: Not used; CompanyName: STMicroelectronics; DrawnBy: Not used; Engineer: Not used; Organization: Not used; Address1: Not used; Address2: Not used; Address3: Not used; Address4: Not used; DocumentNumber: 13; Revision: Not used; SheetNumber: 13; SheetTotal: 15
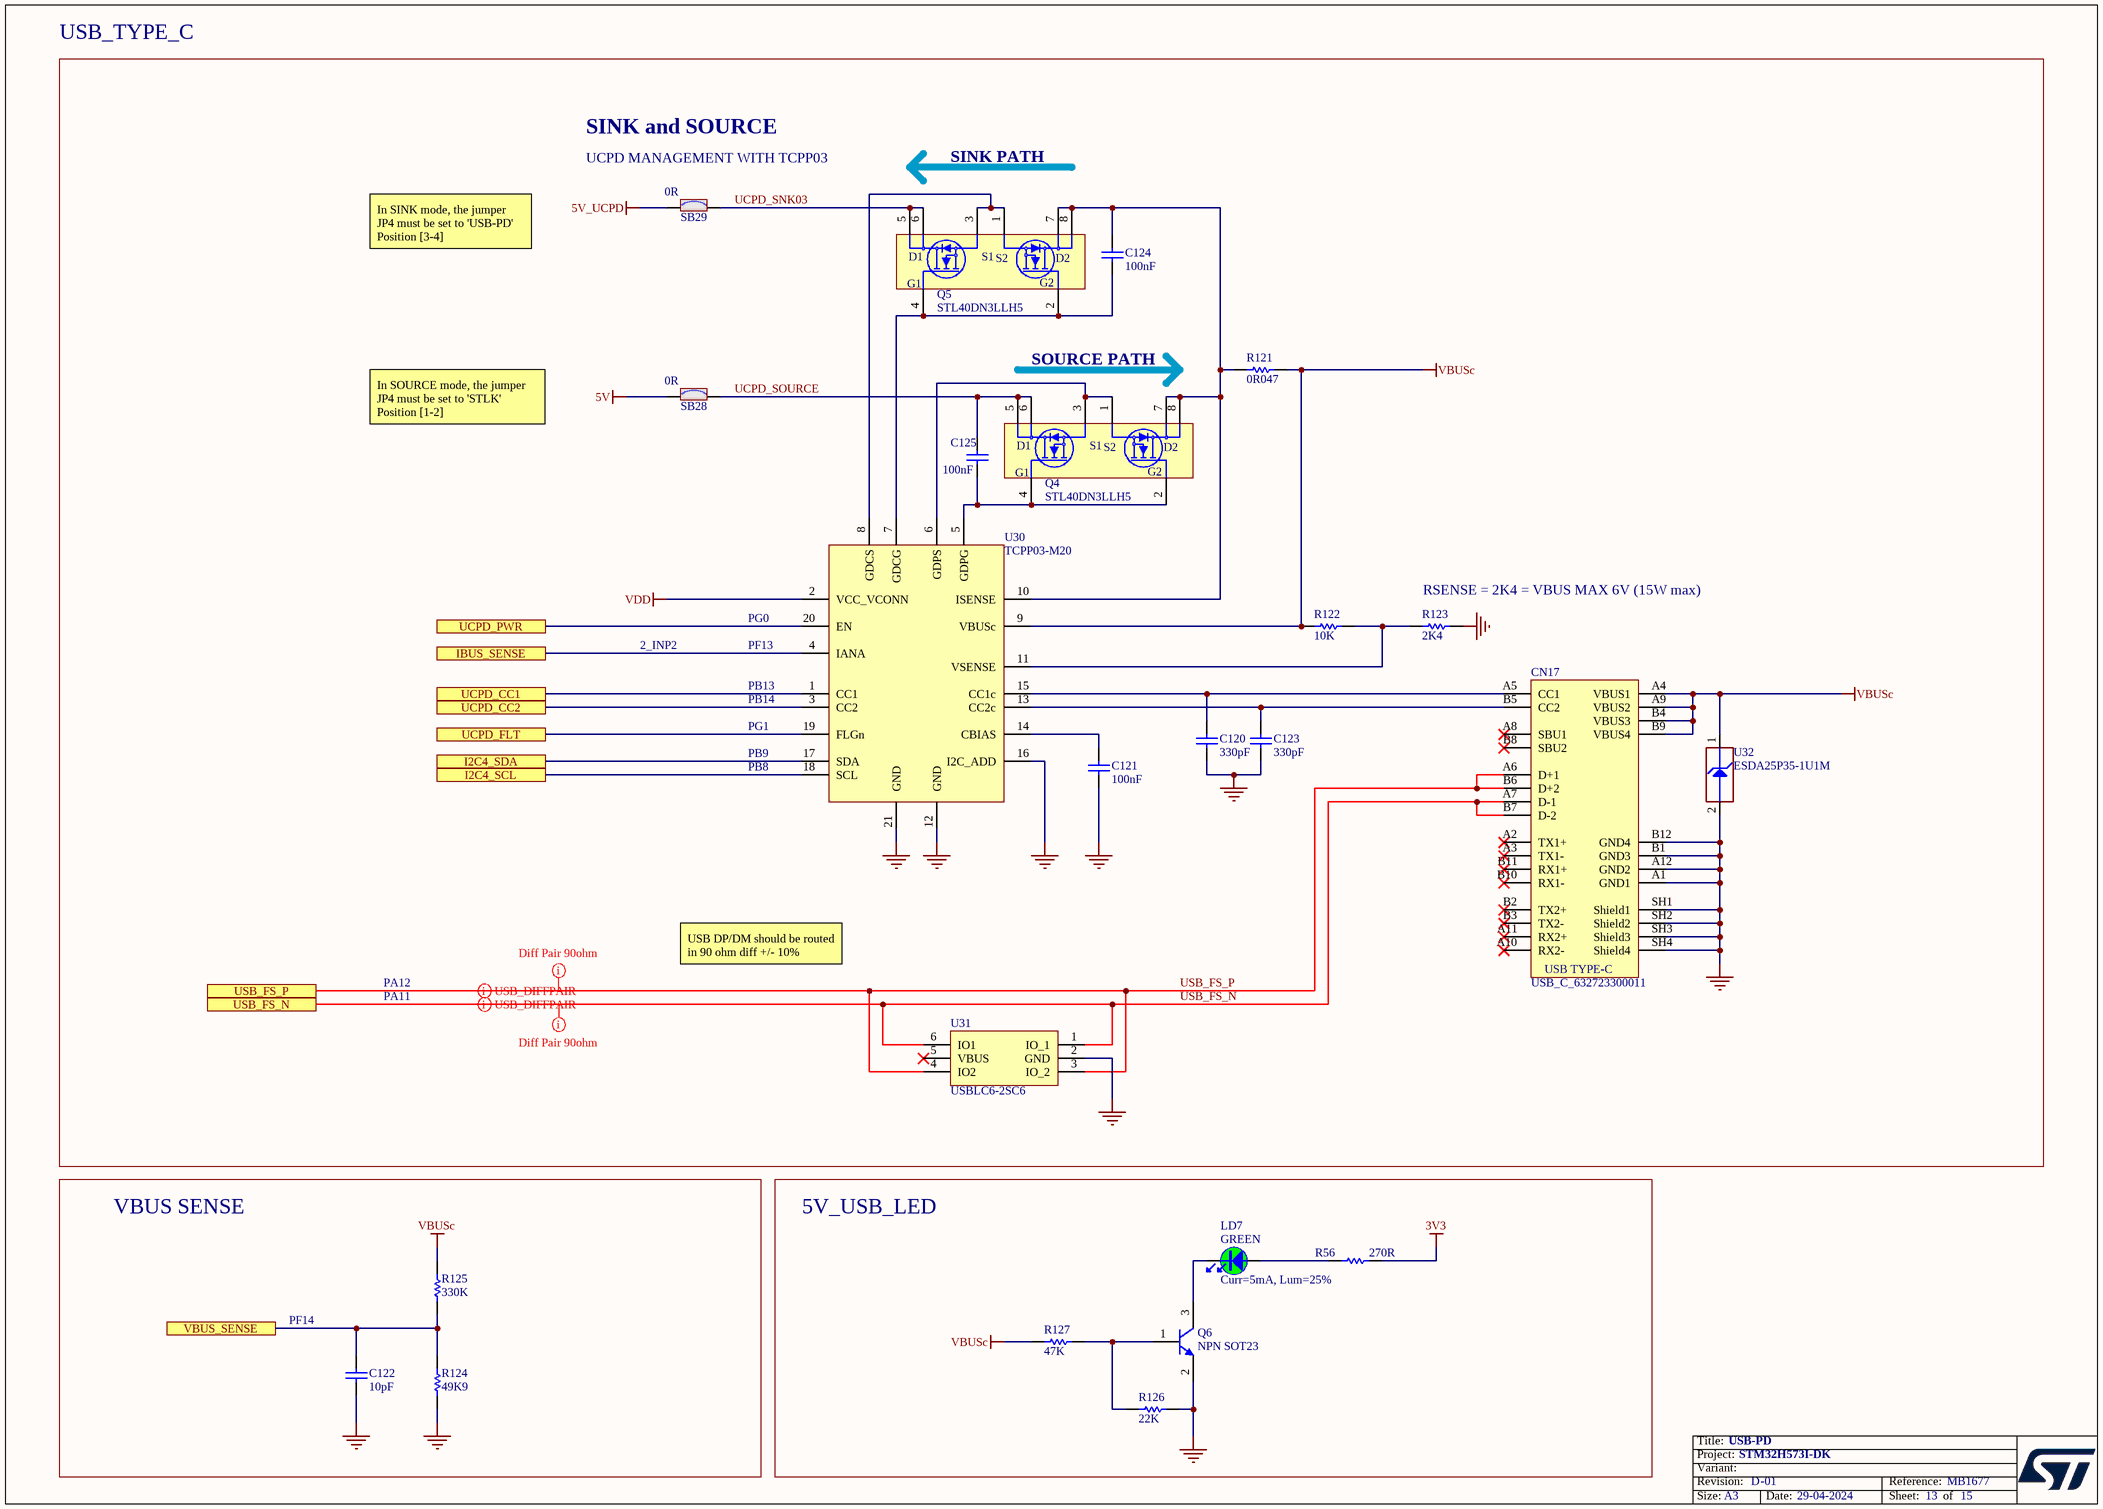
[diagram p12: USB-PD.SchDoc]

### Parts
C120  value 330pF  [C0402]  (hidden comment: Capacitor)
C121  value 100nF  [C0603]
C122  value 10pF  [C0402]
C123  value 330pF  [C0402]  (hidden comment: Capacitor)
C124  value 100nF  [C0603]
C125  value 100nF  [C0603]
CN17  value USB_C_632723300011  [CON_USB-TYPEC_WE_632723300011]  (hidden comment: USB_TYPE_C_Receptacle)
LD7  value GREEN  [LED_0603_OSRAM_LG-Q396-PS-35_GREEN_1A2K_H0P4]
Q4  STL40DN3LLH5  [PowerFLAT_5x6]
Q5  STL40DN3LLH5  [PowerFLAT_5x6]
Q6  value NPN SOT23  [NPN_SOT23]
R56  value 270R  [R0603]
R121  value 0R047  [R0805_H0P5]  (hidden comment: Resistor)
R122  value 10K  [R0402]  (hidden comment: Resistor)
R123  value 2K4  [R0402]  (hidden comment: Resistor)
R124  value 49K9  [R0603]
R125  value 330K  [R0603]
R126  value 22K  [R0603]
R127  value 47K  [R0603]
SB28  value 0R  [SOLDER-BRIDGE_R0603-0R]  (hidden comment: SB_ON)
SB29  value 0R  [SOLDER-BRIDGE_R0603-0R]  (hidden comment: SB_ON)
U30  TCPP03-M20  [ICC_QFN20-EPAD_4X4_P050]
U31  USBLC6-2SC6  [ESD_SOT23-6L]
U32  value ESDA25P35-1U1M  [ESD_QFN1610_2N_1K_2A]

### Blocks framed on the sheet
VBUS SENSE: C122 R124 R125
5V_USB_LED: LD7 Q6 R56 R126 R127

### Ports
I2C4_SCL, I2C4_SDA, IBUS_SENSE, UCPD_CC1, UCPD_CC2, UCPD_FLT, UCPD_PWR, USB_FS_N, USB_FS_P, VBUS_SENSE

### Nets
3V3: R56.2
5V: SB28.1
5V_UCPD: SB29.1
GND: C120.1 C121.2 C122.1 C123.1 CN17.A1(GND1) CN17.A12(GND2) CN17.B1(GND3) CN17.B12(GND4) CN17.SH1(Shield1) CN17.SH2(Shield2) CN17.SH3(Shield3) CN17.SH4(Shield4) Q6.2(E) R123.2 R124.1 R126.2 U30.12(GND) U30.16(I2C_ADD) U30.21(GND) U31.2(GND) U32.2(GND)
VBUSc: CN17.A4(VBUS1) CN17.A9(VBUS2) CN17.B4(VBUS3) CN17.B9(VBUS4) R121.1 R122.1 R125.2 R127.1 U30.9(VBUSc) U32.1(IO1)
VDD: U30.2(VCC_VCONN)
I2C4_SCL: U30.18(SCL) ; port I2C4_SCL
I2C4_SDA: U30.17(SDA) ; port I2C4_SDA
IBUS_SENSE: U30.4(IANA) ; port IBUS_SENSE
UCPD_CC1: U30.1(CC1) ; port UCPD_CC1
UCPD_CC2: U30.3(CC2) ; port UCPD_CC2
UCPD_FLT: U30.19(FLGn) ; port UCPD_FLT
UCPD_PWR: U30.20(EN) ; port UCPD_PWR
UCPD_SNK03: Q5.5(D1) Q5.6(D1) SB29.2
UCPD_SOURCE: C125.2 Q4.5(D1) Q4.6(D1) SB28.2
USB_FS_N: CN17.A7(D-1) CN17.B7(D-2) U31.1(IO_1) U31.6(IO1) ; port USB_FS_N
USB_FS_P: CN17.A6(D+1) CN17.B6(D+2) U31.3(IO_2) U31.4(IO2) ; port USB_FS_P
VBUS_SENSE: C122.2 R124.2 R125.1 ; port VBUS_SENSE
NetC120_2: C120.2 CN17.A5(CC1) U30.15(CC1c)
NetC121_1: C121.1 U30.14(CBIAS)
NetC123_2: C123.2 CN17.B5(CC2) U30.13(CC2c)
NetC124_1: C124.1 Q5.2(G2) Q5.4(G1) U30.7(GDCG)
NetC124_2: C124.2 Q4.7(D2) Q4.8(D2) Q5.7(D2) Q5.8(D2) R121.2 U30.10(ISENSE)
NetC125_1: C125.1 Q4.2(G2) Q4.4(G1) U30.5(GDPG)
NetLD7_1: LD7.1 R56.1
NetLD7_2: LD7.2 Q6.3(C)
NetQ4_1: Q4.1(S2) Q4.3(S1) U30.6(GDPS)
NetQ5_1: Q5.1(S2) Q5.3(S1) U30.8(GDCS)
NetQ6_1: Q6.1(B) R126.1 R127.2
NetR122_2: R122.2 R123.1 U30.11(VSENSE)

Not connected (* = marked no-connect by the designer): CN17 A2(TX1+)* A3(TX1-)* A8(SBU1)* A10(RX2-)* A11(RX2+)* B2(TX2+)* B3(TX2-)* B8(SBU2)* B10(RX1-)* B11(RX1+)*; U31 5(VBUS)*

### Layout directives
mark named Diff Pair 90ohm: USB_FS_N, USB_FS_P
differential pair: USB_FS_N, USB_FS_P

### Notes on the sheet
- USB_TYPE_C
- (near SB29) UCPD MANAGEMENT WITH TCPP03
- SINK and SOURCE
- SINK PATH
- In SINK mode, the jumper JP4 must be set to 'USB-PD' Position [3-4]
- SOURCE PATH
- In SOURCE mode, the jumper JP4 must be set to 'STLK' Position [1-2]
- 2_INP2
- PF13
- PG0
- (near R123) RSENSE = 2K4 = VBUS MAX 6V (15W max)
- PB13
- PB14
- PB9
- PB8
- PG1
- PA12
- USB DP/DM should be routed in 90 ohm diff +/- 10%
- PA11
- PF14
- Curr=5mA, Lum=25%

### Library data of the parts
C120 C123 = MCD-01579: Capacitor, MLCC, 330pF, 50V, NPO, +/-5%, 0402, T=0,5mm; Part_Preference: Recommended; Manufacturer: YAGEO; Manufacturer_Part_Number: CC0402JRNPO9BN331; Component_Country_Of_Origin: China; ID: 3679; ShowFields: YES
C121 = MCD-01099: Capacitor,100nF,50V,X7R,10%,0603; Manufacturer_Part_Number: CC0603KRX7R9BB104; Manufacturer: YAGEO; BMS_Part_Number: 9142278; Part_Preference: Recommended; Provided_By: SUBCO; Component_Country_Of_Origin: China; ID: 3397; Order_Code_RS: 669-8767; ShowFields: YES
C122 = MCD-00015: Capacitor, MLCC, 10pF, 50V, NPO, 5%, 0402, T=0,5mm; Manufacturer_Part_Number: CC0402JRNPO9BN100; Manufacturer: YAGEO; Part_Preference: Recommended; Provided_By: subcon; Initial_Board_Reference: MB1274; Component_Country_Of_Origin: China; ID: 2465; Order_Code_RS: 3019160RL; ShowFields: YES
C124 C125 = MCD-00211: Capacitor, MLCC, 100nF, 16V, X7R, 10%, 0603, T=0,8mm; Manufacturer_Part_Number: CC0603KRX7R7BB104; Manufacturer: YAGEO; Part_Preference: Recommended; Partial_Alternate_Internal_Part_Number: MCD-01099; Provided_By: Subcon; Initial_Board_Reference: MB1319; Component_Country_Of_Origin: China; ID: 2659; Order_Code_RS: 669-8763; ShowFields: YES
CN17 = MCD-02273: USB_TypeC, 24pins, RA, TH, T=1.9mm (USB certified); Part_Type: Connector; Part_Preference: Recommended; Manufacturer: WURTH ELEKTRONIK; Manufacturer_Part_Number: 632723300011; Full_Alternate_Internal_Part_Number: MCD-01108; Component_Country_Of_Origin: China; ShowFields: YES; ID: 4373
LD7 = MCD-00588: LED Green, 0603 SMD, Forward Voltage Typ=2V, Max=2.5V; Part_Type: Display; Manufacturer_Part_Number: LG Q396-PS-35; Manufacturer: OSRAM OPTO SEMICONDUCTORS; Alternate_Manufacturer_Part_Number: VLMTG1300-GS08; Alternate_Manufacturer: VISHAY SEMICONDUCTOR OPTO DIVISION; Part_Preference: Recommended; Partial_Alternate_Internal_Part_Number: MCD-02400, MCD-03155; Provided_By: Subcon; Initial_Board_Reference: MB1331; Component_Country_Of_Origin: Unknown; ID: 3155; ShowFields: YES
Q4 Q5 = MCD-02152: Dual N-channel 30 V, 0.016 Ω typ., 40 A, STripFET™ H5 Power MOSFET; Part_Type: Transistor; Manufacturer: STMICROELECTRONICS; Manufacturer_HQ_COO: EU; Part_Preference: Recommended; ECCN_US: EAR99; ECCN_EU: NEC; Provided_By: SUBCO; Component_Country_Of_Origin: China; ID: 4252; ShowFields: YES
Q6 = MCD-00073: NPN Bipolar Transistor; Part_Type: IC; Manufacturer_Part_Number: BSR14; Manufacturer: ON SEMICONDUCTOR; Part_Preference: Recommended; Partial_Alternate_Internal_Part_Number: MCD-01737, MCD-03305, , MCD-02988; ECCN_US: EAR99; ECCN_EU: NEC; Provided_By: Subcon; Initial_Board_Reference: MB1274; Component_Country_Of_Origin: Unknown; ID: 2519; ShowFields: YES
R56 = MCD-00442: Resistor,270R,0603,1%,1/10W; Manufacturer_Part_Number: RC0603FR-07270RL; Manufacturer: YAGEO; Part_Preference: Recommended; Provided_By: Subcon; Component_Country_Of_Origin: China; ID: 2836; ShowFields: YES
R121 = MCD-02151: Current Detection Resistor, 0R047, 0805, 1%, 1/4W; Manufacturer_Part_Number: RL0805FR-7W0R047L; Manufacturer: YAGEO; Part_Preference: Recommended; ECCN_US: NEC; ECCN_EU: EAR99; Provided_By: SUBCO; Component_Country_Of_Origin: Taiwan; ID: 4251; ShowFields: YES
R122 = MCD-00053: Resistor,10K,0402,1%,1/16W; BMS_Part_Number: 9131590; Part_Preference: Recommended; Manufacturer: YAGEO; Manufacturer_Part_Number: RC0402FR-0710KL; Order_Code_RS: 9239359; Component_Country_Of_Origin: China; ID: 2539; ShowFields: YES
R123 = MCD-00433: Resistor,2K4,0402,1%,1/16W; Part_Preference: Recommended; Manufacturer: YAGEO; Manufacturer_Part_Number: RC0402FR-072K4L; Component_Country_Of_Origin: China; ID: 2843; ShowFields: YES
R124 = MCD-01171: Resistor,49K9,0603,1%; Manufacturer_Part_Number: RC0603FR-0749K9L; Manufacturer: YAGEO; Part_Preference: Recommended; Provided_By: Subcon; Initial_Board_Reference: MB1397; Component_Country_Of_Origin: China; ID: 3324; ShowFields: YES
R125 = MCD-00458: Resistor,330K,0603,1%,1/10W; Manufacturer_Part_Number: RC0603FR-07330KL; Manufacturer: YAGEO; Part_Preference: Recommended; Provided_By: Subcon; Component_Country_Of_Origin: China; ID: 2819; ShowFields: YES
R126 = MCD-00430: Resistor,22K,0603,1%,1/10W; Manufacturer_Part_Number: RC0603FR-0722KL; Manufacturer: YAGEO; Part_Preference: Recommended; Provided_By: Subcon; Component_Country_Of_Origin: China; ID: 2847; ShowFields: YES
R127 = MCD-00222: Resistor,47K,0603,1%,1/10W; Manufacturer_Part_Number: RC0603FR-0747KL; Manufacturer: YAGEO; Part_Preference: Recommended; Provided_By: Subcon; Initial_Board_Reference: MB1319; Component_Country_Of_Origin: China; ID: 2645; ShowFields: YES
SB28 SB29 = MCD-00071: as SB10 on sheet Board_power
U30 = MCD-02130: USB Type-C Port Protection for USB DRP Power Delivery, PPS compliant; Part_Type: IC; Manufacturer: STMICROELECTRONICS; Manufacturer_HQ_COO: EU; Part_Preference: Recommended; ECCN_US: EAR99; ECCN_EU: NEC; Provided_By: SUBCO with ST control; Component_Country_Of_Origin: China; ID: 4230; ShowFields: YES
U31 = MCD-00163: Very low capacitance ESD protection; Part_Type: Diode; Manufacturer: STMICROELECTRONICS; BMS_Part_Number: 9151075; Part_Preference: Recommended; ECCN_US: EAR99; ECCN_EU: NEC; Provided_By: SUBCO with ST control; Component_Country_Of_Origin: China; ID: 2707; Order_Code_RS: 920-6266; ShowFields: YES
U32 = MCD-01207: High power Transient voltage suppressor:25V/35A EOS and ESD transients protection.; Part_Type: Diode; Manufacturer: STMICROELECTRONICS; BMS_Part_Number: 9179045; Manufacturer_HQ_COO: EU; Part_Preference: Recommended; ECCN_US: EAR99; ECCN_EU: NEC; Provided_By: SUBCO with ST control; Component_Country_Of_Origin: China; ID: 3289; Order_Code_RS: 163-9774; ShowFields: YES

## Sheet microSDcard.SchDoc: microSD Card
size A4; Date: Not used; ApprovedBy: Not used; CheckedBy: Not used; Author: Not used; CompanyName: STMicroelectronics; DrawnBy: Not used; Engineer: Not used; Organization: Not used; Address1: Not used; Address2: Not used; Address3: Not used; Address4: Not used; DocumentNumber: 7; Revision: Not used; SheetNumber: 7; SheetTotal: 15
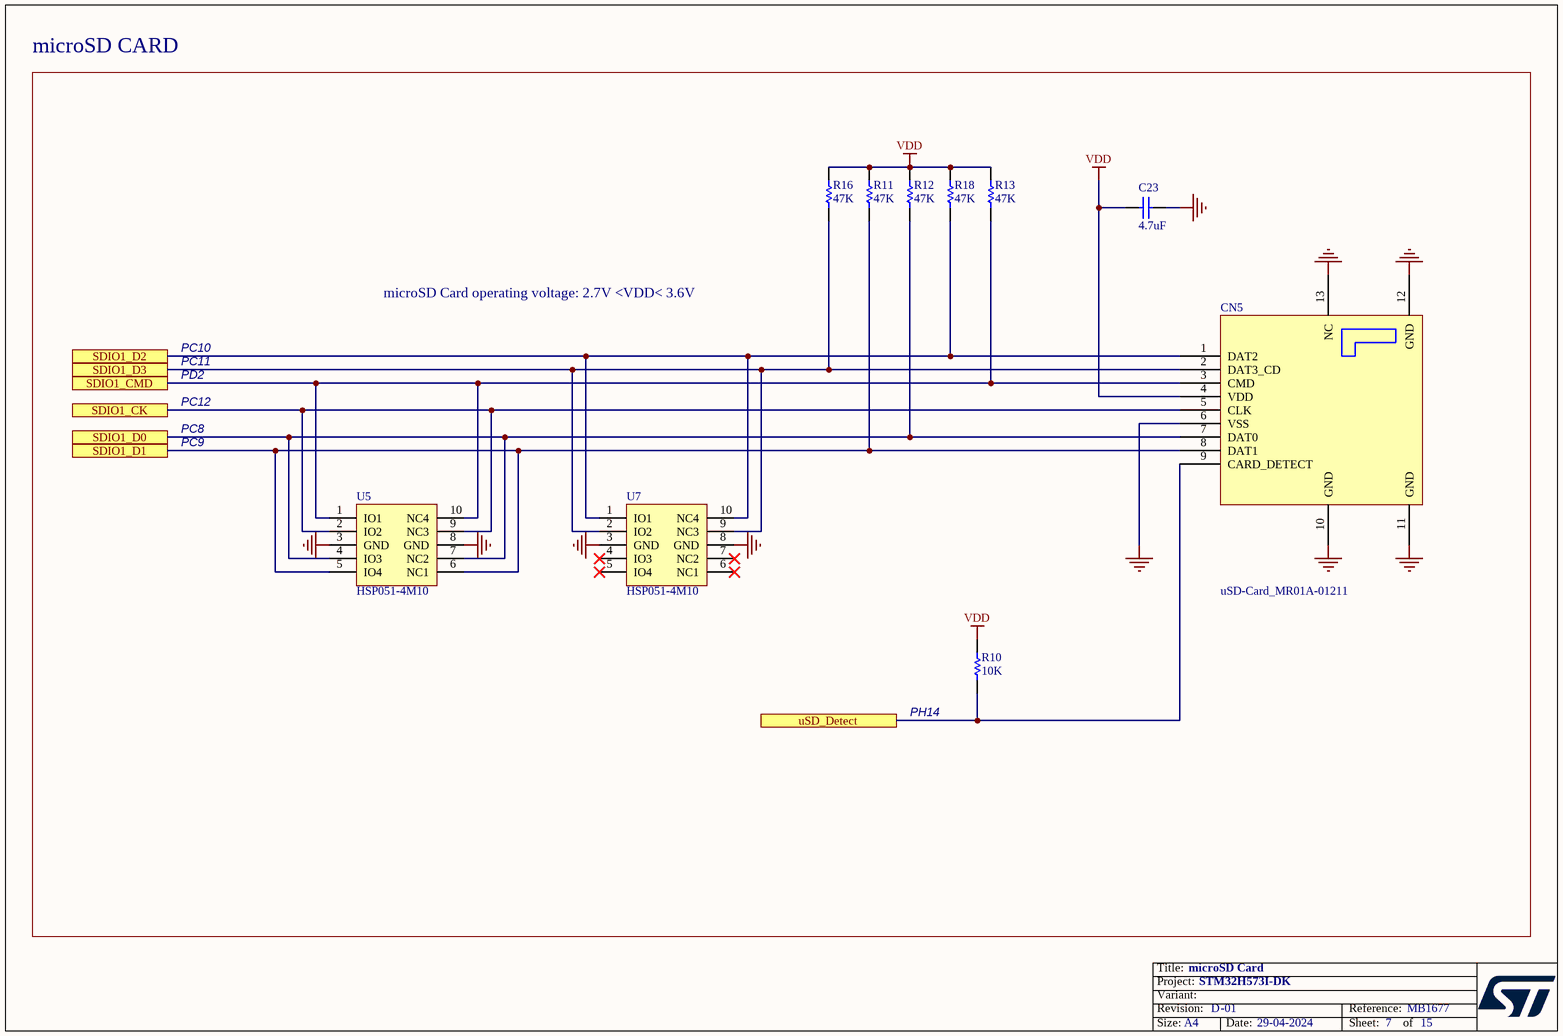
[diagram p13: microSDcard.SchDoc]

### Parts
C23  value 4.7uF  [C0603_H0P8]  (hidden comment: Capacitor)
CN5  value uSD-Card_MR01A-01211  [CON_MICROSD_ATOM_MR01A-01211]  (hidden comment: MR01A-01211)
R10  value 10K  [R0603]  (hidden comment: Resistor)
R11  value 47K  [R0402]  (hidden comment: Resistor)
R12  value 47K  [R0402]  (hidden comment: Resistor)
R13  value 47K  [R0402]  (hidden comment: Resistor)
R16  value 47K  [R0402]  (hidden comment: Resistor)
R18  value 47K  [R0402]  (hidden comment: Resistor)
U5  HSP051-4M10  [ESD_UQFN-10L_2P5X1_P050]
U7  HSP051-4M10  [ESD_UQFN-10L_2P5X1_P050]

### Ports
SDIO1_CK, SDIO1_CMD, SDIO1_D0, SDIO1_D1, SDIO1_D2, SDIO1_D3, uSD_Detect

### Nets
GND: C23.2 CN5.6(VSS) CN5.10(GND) CN5.11(GND) CN5.12(GND) CN5.13(NC) U5.3(GND) U5.8(GND) U7.3(GND) U7.8(GND)
VDD: C23.1 CN5.4(VDD) R10.2 R11.2 R12.2 R13.2 R16.2 R18.2
SDIO1_CK: CN5.5(CLK) U5.2(IO2) U5.9(NC3) ; port SDIO1_CK
SDIO1_CMD: CN5.3(CMD) R13.1 U5.1(IO1) U5.10(NC4) ; port SDIO1_CMD
SDIO1_D0: CN5.7(DAT0) R12.1 U5.4(IO3) U5.7(NC2) ; port SDIO1_D0
SDIO1_D1: CN5.8(DAT1) R11.1 U5.5(IO4) U5.6(NC1) ; port SDIO1_D1
SDIO1_D2: CN5.1(DAT2) R18.1 U7.1(IO1) U7.10(NC4) ; port SDIO1_D2
SDIO1_D3: CN5.2(DAT3_CD) R16.1 U7.2(IO2) U7.9(NC3) ; port SDIO1_D3
uSD_Detect: CN5.9(CARD_DETECT) R10.1 ; port uSD_Detect

Not connected (* = marked no-connect by the designer): U7 4(IO3)* 5(IO4)* 6(NC1)* 7(NC2)*

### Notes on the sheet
- microSD CARD
- microSD Card operating voltage: 2.7V <VDD< 3.6V
- PC10
- PC11
- PD2
- PC8
- PC9
- PC12
- (near R10) PH14

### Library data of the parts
C23 = MCD-01721: Capacitor, 4.7uF, 10V, X5R, 10%, 0603, T=0.8mm; Manufacturer_Part_Number: CC0603KRX5R6BB475; Manufacturer: YAGEO; Part_Preference: Recommended; Provided_By: SUBCO; Component_Country_Of_Origin: China; ID: 3821; ShowFields: YES
CN5 = MCD-00653: Connector_uSD Card, Top Mnt Push-Push; Part_Preference: Recommended; Manufacturer: ATOM; Component_Country_Of_Origin: Unknown; ShowFields: YES; ID: 3087
R10 = MCD-00220: Resistor,10K,0603,1%,1/10W; Manufacturer_Part_Number: RC0603FR-0710KL; Manufacturer: YAGEO; Part_Preference: Recommended; Provided_By: SUBCO; Component_Country_Of_Origin: China; ID: 2649; ShowFields: YES
R11-R13 R16 R18 = MCD-00063: Resistor,47K,0402,1%,1/16W; Manufacturer_Part_Number: RC0402FR-0747KL; Manufacturer: YAGEO; Part_Preference: Recommended; Provided_By: SUBCO; Component_Country_Of_Origin: China; ID: 2528; Order_Code_RS: 9239430; ShowFields: YES
U5 U7 = MCD-00667: 4-line ESD protection for high speed lines; Part_Type: Diode; Manufacturer: STMICROELECTRONICS; BMS_Part_Number: 9179041; Manufacturer_HQ_COO: EU; Part_Preference: Recommended; Provided_By: SUBCO with ST control; Component_Country_Of_Origin: Philippines; ID: 3081; ShowFields: YES

## Sheet NOR_Flash_memory.SchDoc: NOR Flash memory
size A4; Date: Not used; ApprovedBy: Not used; CheckedBy: Not used; Author: Not used; CompanyName: STMicroelectronics; DrawnBy: Not used; Engineer: Not used; Organization: Not used; Address1: Not used; Address2: Not used; Address3: Not used; Address4: Not used; DocumentNumber: 6; Revision: Not used; SheetNumber: 6; SheetTotal: 15
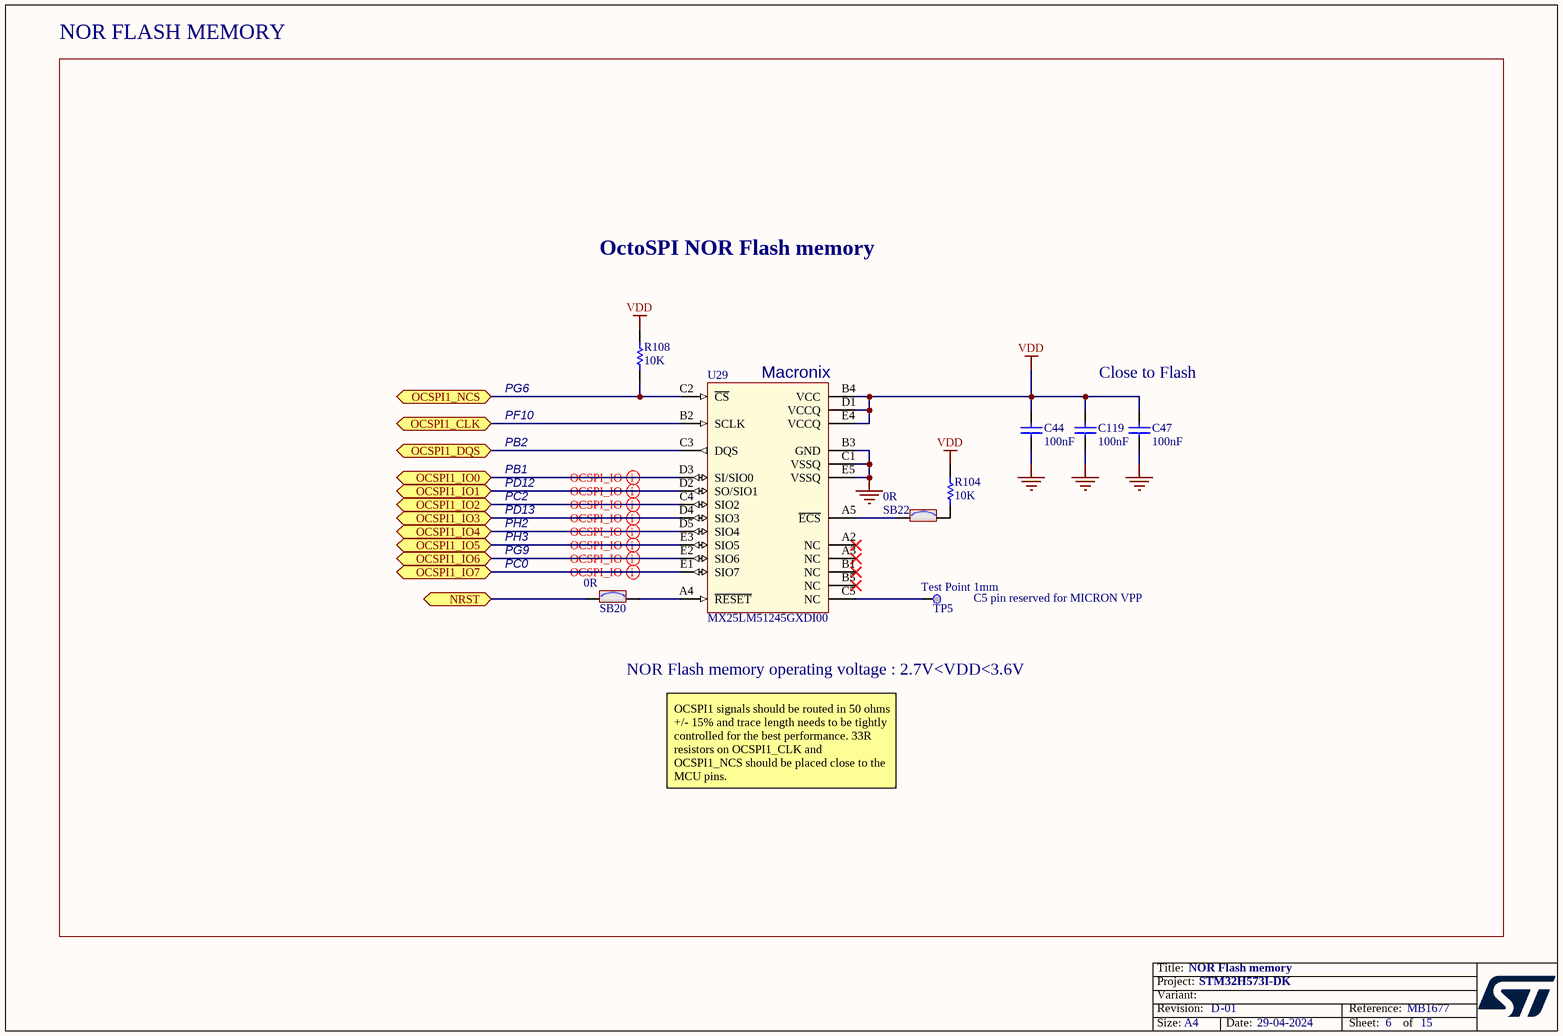
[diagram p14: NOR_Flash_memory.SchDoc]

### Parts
C44  value 100nF  [C0402]  (hidden comment: Capacitor)
C47  value 100nF  [C0402]  (hidden comment: Capacitor)
C119  value 100nF  [C0402]  (hidden comment: Capacitor)
R104  value 10K  [R0402]  (hidden comment: Resistor)
R108  value 10K  [R0402]  (hidden comment: Resistor)
SB20  value 0R  [SOLDER-BRIDGE_R0603-0R]  (hidden comment: SB_ON)
SB22  value 0R  [SOLDER-BRIDGE_R0603-0R]  (hidden comment: SB_ON)
TP5  value Test Point 1mm  [TP_SMD_1MM]  (hidden comment: Test Point)  (no BOM)
U29  MX25LM51245GXDI00  [ICC_BGA24_5X5-BALL-ARRAY_6X8_P1]

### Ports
NRST (bidir), OCSPI1_CLK (bidir), OCSPI1_DQS (bidir), OCSPI1_IO0 (bidir), OCSPI1_IO1 (bidir), OCSPI1_IO2 (bidir), OCSPI1_IO3 (bidir), OCSPI1_IO4 (bidir), OCSPI1_IO5 (bidir), OCSPI1_IO6 (bidir), OCSPI1_IO7 (bidir), OCSPI1_NCS (bidir)

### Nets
GND: C44.1 C47.1 C119.1 U29.B3(GND) U29.C1(VSSQ) U29.E5(VSSQ)
VDD: C44.2 C47.2 C119.2 R104.2 R108.1 U29.B4(VCC) U29.D1(VCCQ) U29.E4(VCCQ)
NRST: SB20.1 ; port NRST
OCSPI1_CLK: U29.B2(SCLK) ; port OCSPI1_CLK
OCSPI1_DQS: U29.C3(DQS) ; port OCSPI1_DQS
OCSPI1_IO0: U29.D3(SI/SIO0) ; port OCSPI1_IO0
OCSPI1_IO1: U29.D2(SO/SIO1) ; port OCSPI1_IO1
OCSPI1_IO2: U29.C4(SIO2) ; port OCSPI1_IO2
OCSPI1_IO3: U29.D4(SIO3) ; port OCSPI1_IO3
OCSPI1_IO4: U29.D5(SIO4) ; port OCSPI1_IO4
OCSPI1_IO5: U29.E3(SIO5) ; port OCSPI1_IO5
OCSPI1_IO6: U29.E2(SIO6) ; port OCSPI1_IO6
OCSPI1_IO7: U29.E1(SIO7) ; port OCSPI1_IO7
OCSPI1_NCS: R108.2 U29.C2(~{CS}) ; port OCSPI1_NCS
NetR104_1: R104.1 SB22.2
NetSB20_2: SB20.2 U29.A4(~{RESET})
NetSB22_1: SB22.1 U29.A5(~{ECS})
NetTP5_1: TP5.1 U29.C5(NC)

Not connected (* = marked no-connect by the designer): U29 A2(NC)* A3(NC)* B1(NC)* B5(NC)*

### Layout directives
rule Undefined; rule ? ; rule ? : OCSPI1_IO0, OCSPI1_IO1, OCSPI1_IO2, OCSPI1_IO3, OCSPI1_IO4, OCSPI1_IO5, OCSPI1_IO6, OCSPI1_IO7

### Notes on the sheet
- NOR FLASH MEMORY
- OctoSPI NOR Flash memory
- (near U29) Macronix
- Close to Flash
- PG6
- PF10
- PB2
- PB1
- PD13
- PC2
- PD12
- PH3
- PH2
- PG9
- PC0
- (near TP5) C5 pin reserved for MICRON VPP
- NOR Flash memory operating voltage : 2.7V<VDD<3.6V
- OCSPI1 signals should be routed in 50 ohms +/- 15% and trace length needs to be tightly controlled for the best performance. 33R resistors on OCSPI1_CLK and OCSPI1_NCS should be placed close to the MCU pins.

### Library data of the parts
C44 C47 C119 = MCD-00006: as C26 on sheet Board_power
R104 R108 = MCD-00053: as R17 on sheet Board_power
SB20 SB22 = MCD-00071: as SB10 on sheet Board_power
TP5 = MCD-00074: Test Point 1mm; Part_Type: Misc; Part_Preference: Recommended; Component_Country_Of_Origin: Unknown; ID: 2518; ShowFields: YES
U29 = MCD-00246: Memory,Octo-SPI-NOR,512Mb,2048x16,133MHz,3V,DTR,BGA24, CMOS MXSMIO; Part_Type: IC; Manufacturer: MACRONIX; Part_Preference: Recommended; ECCN_US: 3A991.b.1.a; Provided_By: SUBCO; Component_Country_Of_Origin: Taiwan°; ID: 2623; ShowFields: YES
